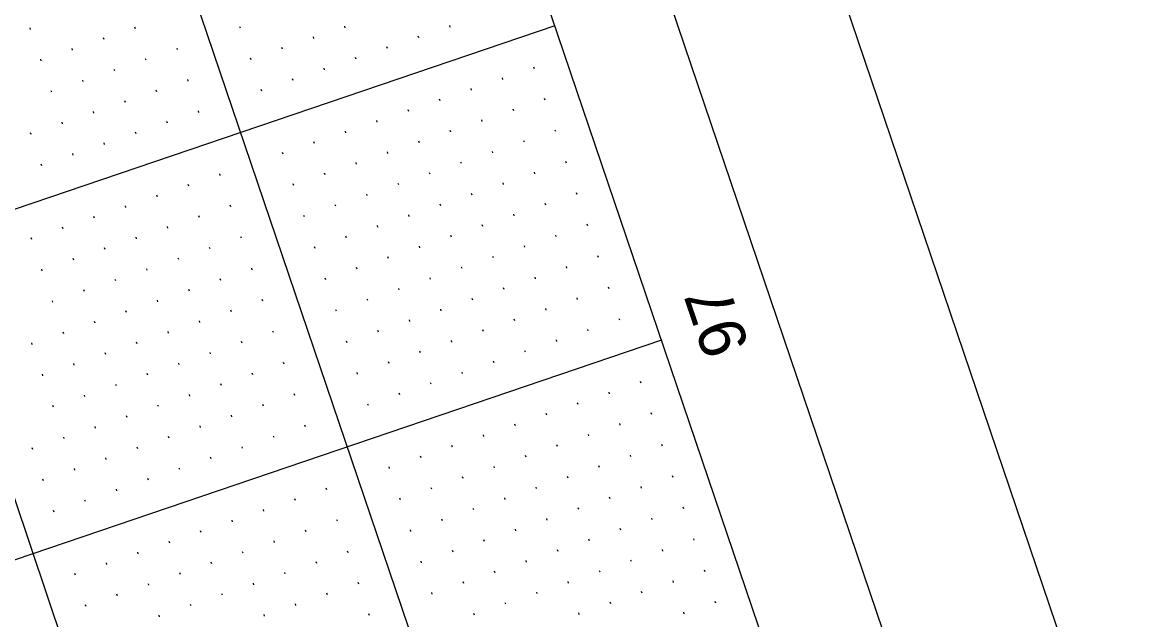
# Model space of a CAD drawing. Extents: x 2150318 to 2152065, y 143281 to 145371.
# Drawn here: x 2151482.1 to 2151649.1, y 144649.2 to 144739.2 of the extents above; entities that cross this region are included whole.
import ezdxf

# ---------------------------------------------------------------- set-up
doc = ezdxf.new("R2010")
doc.units = 0
for name, color, linetype in [('SHT_Plan_Profile_Sheet_Sta_Txt', 7, 'Continuous'), ('SHT_Plot_Shape_Half', 7, 'Continuous'), ('SHT_Profile_Grid_Major', 7, 'Continuous'), ('SHT_Profile_Grid_Minor', 7, 'Continuous'), ('SHT_Sheet_Border', 7, 'Continuous')]:
    doc.layers.add(name, color=color, linetype=linetype)

msp = doc.modelspace()

# ---------------------------------------------------------------- linework, layer by layer
at = {"layer": 'SHT_Plot_Shape_Half'}
msp.add_lwpolyline([(2150909.49, 143371.4), (2150363.35, 144981.29), (2151405.04, 145334.68), (2151951.18, 143724.79)], close=True, dxfattribs=at)
at = {"layer": 'SHT_Profile_Grid_Major'}
for p, q in [((2151832.26, 143787.41), (2151326.27, 145278.92)), ((2151784.91, 143771.34), (2151278.93, 145262.85)), ((2151562.37, 144738.62), (2151088.87, 144577.99)), ((2151578.43, 144691.27), (2151147.55, 144545.1))]:
    msp.add_line(p, q, dxfattribs=at)
at = {"layer": 'SHT_Profile_Grid_Minor'}
for p, q in [((2151483.35, 144738.08), (2151483.27, 144738.32)), ((2151499.16, 144738.17), (2151499.08, 144738.41)), ((2151514.97, 144738.25), (2151514.89, 144738.49)), ((2151530.78, 144738.34), (2151530.7, 144738.57)), ((2151546.6, 144738.42), (2151546.51, 144738.66)), ((2151494.43, 144736.56), (2151494.35, 144736.8)), ((2151526.05, 144736.73), (2151525.97, 144736.97)), ((2151541.86, 144736.81), (2151541.78, 144737.05)), ((2151489.69, 144734.96), (2151489.61, 144735.19)), ((2151505.5, 144735.04), (2151505.42, 144735.28)), ((2151521.31, 144735.12), (2151521.23, 144735.36)), ((2151537.13, 144735.21), (2151537.04, 144735.44)), ((2151484.96, 144733.35), (2151484.88, 144733.59)), ((2151500.77, 144733.43), (2151500.69, 144733.67)), ((2151516.58, 144733.52), (2151516.5, 144733.75)), ((2151532.39, 144733.6), (2151532.31, 144733.84)), ((2151496.03, 144731.83), (2151495.95, 144732.06)), ((2151527.66, 144732), (2151527.58, 144732.23)), ((2151559.28, 144732.16), (2151559.2, 144732.4)), ((2151491.3, 144730.22), (2151491.22, 144730.46)), ((2151507.11, 144730.3), (2151507.03, 144730.54)), ((2151522.92, 144730.39), (2151522.84, 144730.63)), ((2151554.54, 144730.56), (2151554.46, 144730.79)), ((2151486.56, 144728.61), (2151486.48, 144728.85)), ((2151502.37, 144728.7), (2151502.29, 144728.94)), ((2151518.19, 144728.78), (2151518.11, 144729.02)), ((2151549.81, 144728.95), (2151549.73, 144729.19)), ((2151497.64, 144727.09), (2151497.56, 144727.33)), ((2151545.07, 144727.34), (2151544.99, 144727.58)), ((2151556.15, 144725.82), (2151556.07, 144726.06)), ((2151560.88, 144727.43), (2151560.8, 144727.67)), ((2151492.9, 144725.49), (2151492.82, 144725.72)), ((2151508.72, 144725.57), (2151508.64, 144725.81)), ((2151535.6, 144724.13), (2151535.52, 144724.37)), ((2151540.34, 144725.74), (2151540.26, 144725.97)), ((2151551.41, 144724.22), (2151551.33, 144724.45)), ((2151488.17, 144723.88), (2151488.09, 144724.12)), ((2151503.98, 144723.96), (2151503.9, 144724.2)), ((2151530.87, 144722.53), (2151530.79, 144722.76)), ((2151546.68, 144722.61), (2151546.6, 144722.85)), ((2151562.49, 144722.69), (2151562.41, 144722.93)), ((2151483.43, 144722.27), (2151483.35, 144722.51)), ((2151499.25, 144722.36), (2151499.17, 144722.59)), ((2151526.13, 144720.92), (2151526.05, 144721.16)), ((2151541.94, 144721), (2151541.86, 144721.24)), ((2151557.76, 144721.09), (2151557.68, 144721.32)), ((2151489.78, 144719.14), (2151489.7, 144719.38)), ((2151494.51, 144720.75), (2151494.43, 144720.99)), ((2151521.4, 144719.31), (2151521.32, 144719.55)), ((2151537.21, 144719.4), (2151537.13, 144719.63)), ((2151553.02, 144719.48), (2151552.94, 144719.72)), ((2151485.04, 144717.54), (2151484.96, 144717.78)), ((2151532.47, 144717.79), (2151532.39, 144718.03)), ((2151548.29, 144717.87), (2151548.21, 144718.11)), ((2151564.1, 144717.96), (2151564.02, 144718.2)), ((2151511.93, 144716.1), (2151511.85, 144716.34)), ((2151527.74, 144716.18), (2151527.66, 144716.42)), ((2151543.55, 144716.27), (2151543.47, 144716.5)), ((2151559.36, 144716.35), (2151559.28, 144716.59)), ((2151507.19, 144714.49), (2151507.11, 144714.73)), ((2151523, 144714.58), (2151522.92, 144714.81)), ((2151538.82, 144714.66), (2151538.74, 144714.9)), ((2151554.63, 144714.75), (2151554.55, 144714.98)), ((2151502.46, 144712.89), (2151502.38, 144713.12)), ((2151534.08, 144713.06), (2151534, 144713.29)), ((2151549.89, 144713.14), (2151549.81, 144713.38)), ((2151565.7, 144713.22), (2151565.62, 144713.46)), ((2151497.72, 144711.28), (2151497.64, 144711.52)), ((2151513.53, 144711.37), (2151513.45, 144711.6)), ((2151529.35, 144711.45), (2151529.27, 144711.69)), ((2151545.16, 144711.53), (2151545.08, 144711.77)), ((2151560.97, 144711.62), (2151560.89, 144711.85)), ((2151492.99, 144709.67), (2151492.91, 144709.91)), ((2151508.8, 144709.76), (2151508.72, 144710)), ((2151524.61, 144709.84), (2151524.53, 144710.08)), ((2151540.42, 144709.93), (2151540.34, 144710.16)), ((2151556.23, 144710.01), (2151556.15, 144710.25)), ((2151488.25, 144708.07), (2151488.17, 144708.31)), ((2151504.06, 144708.15), (2151503.98, 144708.39)), ((2151535.69, 144708.32), (2151535.61, 144708.56)), ((2151551.5, 144708.4), (2151551.42, 144708.64)), ((2151567.31, 144708.49), (2151567.23, 144708.73)), ((2151483.52, 144706.46), (2151483.44, 144706.7)), ((2151499.33, 144706.55), (2151499.25, 144706.78)), ((2151515.14, 144706.63), (2151515.06, 144706.87)), ((2151530.95, 144706.71), (2151530.87, 144706.95)), ((2151546.76, 144706.8), (2151546.68, 144707.03)), ((2151562.57, 144706.88), (2151562.49, 144707.12)), ((2151494.59, 144704.94), (2151494.51, 144705.18)), ((2151510.41, 144705.02), (2151510.33, 144705.26)), ((2151526.22, 144705.11), (2151526.14, 144705.34)), ((2151542.03, 144705.19), (2151541.95, 144705.43)), ((2151557.84, 144705.28), (2151557.76, 144705.51)), ((2151489.86, 144703.33), (2151489.78, 144703.57)), ((2151505.67, 144703.42), (2151505.59, 144703.65)), ((2151537.29, 144703.59), (2151537.21, 144703.82)), ((2151553.1, 144703.67), (2151553.02, 144703.91)), ((2151568.92, 144703.75), (2151568.84, 144703.99)), ((2151485.12, 144701.73), (2151485.04, 144701.96)), ((2151500.94, 144701.81), (2151500.86, 144702.05)), ((2151516.75, 144701.9), (2151516.67, 144702.13)), ((2151532.56, 144701.98), (2151532.48, 144702.22)), ((2151548.37, 144702.06), (2151548.29, 144702.3)), ((2151564.18, 144702.15), (2151564.1, 144702.38)), ((2151496.2, 144700.2), (2151496.12, 144700.44)), ((2151512.01, 144700.29), (2151511.93, 144700.53)), ((2151527.82, 144700.37), (2151527.74, 144700.61)), ((2151543.63, 144700.46), (2151543.55, 144700.69)), ((2151559.45, 144700.54), (2151559.37, 144700.78)), ((2151491.47, 144698.6), (2151491.39, 144698.84)), ((2151507.28, 144698.68), (2151507.2, 144698.92)), ((2151538.9, 144698.85), (2151538.82, 144699.09)), ((2151554.71, 144698.93), (2151554.63, 144699.17)), ((2151565.79, 144697.41), (2151565.71, 144697.65)), ((2151570.52, 144699.02), (2151570.44, 144699.26)), ((2151486.73, 144696.99), (2151486.65, 144697.23)), ((2151502.54, 144697.08), (2151502.46, 144697.31)), ((2151518.35, 144697.16), (2151518.27, 144697.4)), ((2151534.16, 144697.24), (2151534.08, 144697.48)), ((2151545.24, 144695.72), (2151545.16, 144695.96)), ((2151549.98, 144697.33), (2151549.9, 144697.57)), ((2151561.05, 144695.81), (2151560.97, 144696.04)), ((2151497.81, 144695.47), (2151497.73, 144695.71)), ((2151513.62, 144695.55), (2151513.54, 144695.79)), ((2151529.43, 144695.64), (2151529.35, 144695.87)), ((2151540.51, 144694.12), (2151540.43, 144694.35)), ((2151556.32, 144694.2), (2151556.24, 144694.44)), ((2151572.13, 144694.28), (2151572.05, 144694.52)), ((2151493.07, 144693.86), (2151492.99, 144694.1)), ((2151508.88, 144693.95), (2151508.8, 144694.18)), ((2151519.96, 144692.43), (2151519.88, 144692.66)), ((2151535.77, 144692.51), (2151535.69, 144692.75)), ((2151551.58, 144692.59), (2151551.5, 144692.83)), ((2151567.39, 144692.68), (2151567.31, 144692.91)), ((2151488.34, 144692.26), (2151488.26, 144692.49)), ((2151499.41, 144690.74), (2151499.33, 144690.97)), ((2151504.15, 144692.34), (2151504.07, 144692.58)), ((2151515.22, 144690.82), (2151515.14, 144691.06)), ((2151531.04, 144690.9), (2151530.96, 144691.14)), ((2151546.85, 144690.99), (2151546.77, 144691.22)), ((2151562.66, 144691.07), (2151562.58, 144691.31)), ((2151483.6, 144690.65), (2151483.52, 144690.89)), ((2151494.68, 144689.13), (2151494.6, 144689.37)), ((2151510.49, 144689.21), (2151510.41, 144689.45)), ((2151542.11, 144689.38), (2151542.03, 144689.62)), ((2151557.92, 144689.46), (2151557.84, 144689.7)), ((2151489.94, 144687.52), (2151489.86, 144687.76)), ((2151505.75, 144687.61), (2151505.67, 144687.84)), ((2151521.57, 144687.69), (2151521.49, 144687.93)), ((2151537.38, 144687.77), (2151537.3, 144688.01)), ((2151553.19, 144687.86), (2151553.11, 144688.1)), ((2151485.21, 144685.92), (2151485.13, 144686.15)), ((2151501.02, 144686), (2151500.94, 144686.24)), ((2151516.83, 144686.08), (2151516.75, 144686.32)), ((2151532.64, 144686.17), (2151532.56, 144686.4)), ((2151548.45, 144686.25), (2151548.37, 144686.49)), ((2151496.29, 144684.39), (2151496.2, 144684.63)), ((2151512.1, 144684.48), (2151512.02, 144684.71)), ((2151543.72, 144684.65), (2151543.64, 144684.88)), ((2151575.34, 144684.81), (2151575.26, 144685.05)), ((2151491.55, 144682.79), (2151491.47, 144683.02)), ((2151507.36, 144682.87), (2151507.28, 144683.11)), ((2151523.17, 144682.96), (2151523.09, 144683.19)), ((2151538.98, 144683.04), (2151538.9, 144683.28)), ((2151570.61, 144683.21), (2151570.53, 144683.44)), ((2151486.82, 144681.18), (2151486.73, 144681.42)), ((2151502.63, 144681.27), (2151502.55, 144681.5)), ((2151518.44, 144681.35), (2151518.36, 144681.59)), ((2151534.25, 144681.43), (2151534.17, 144681.67)), ((2151565.87, 144681.6), (2151565.79, 144681.84)), ((2151497.89, 144679.66), (2151497.81, 144679.9)), ((2151513.7, 144679.74), (2151513.62, 144679.98)), ((2151561.14, 144679.99), (2151561.06, 144680.23)), ((2151576.95, 144680.08), (2151576.87, 144680.32)), ((2151493.16, 144678.05), (2151493.08, 144678.29)), ((2151508.97, 144678.14), (2151508.89, 144678.37)), ((2151524.78, 144678.22), (2151524.7, 144678.46)), ((2151556.4, 144678.39), (2151556.32, 144678.63)), ((2151572.21, 144678.47), (2151572.13, 144678.71)), ((2151488.42, 144676.45), (2151488.34, 144676.68)), ((2151504.23, 144676.53), (2151504.15, 144676.77)), ((2151520.04, 144676.61), (2151519.96, 144676.85)), ((2151551.67, 144676.78), (2151551.59, 144677.02)), ((2151567.48, 144676.87), (2151567.4, 144677.1)), ((2151483.69, 144674.84), (2151483.61, 144675.08)), ((2151499.5, 144674.92), (2151499.42, 144675.16)), ((2151515.31, 144675.01), (2151515.23, 144675.24)), ((2151546.93, 144675.18), (2151546.85, 144675.41)), ((2151562.74, 144675.26), (2151562.66, 144675.5)), ((2151578.55, 144675.34), (2151578.47, 144675.58)), ((2151494.76, 144673.32), (2151494.68, 144673.55)), ((2151510.57, 144673.4), (2151510.49, 144673.64)), ((2151542.2, 144673.57), (2151542.12, 144673.81)), ((2151558.01, 144673.65), (2151557.93, 144673.89)), ((2151573.82, 144673.74), (2151573.74, 144673.97)), ((2151490.03, 144671.71), (2151489.95, 144671.95)), ((2151505.84, 144671.8), (2151505.76, 144672.03)), ((2151537.46, 144671.96), (2151537.38, 144672.2)), ((2151553.27, 144672.05), (2151553.19, 144672.28)), ((2151569.08, 144672.13), (2151569, 144672.37)), ((2151485.29, 144670.1), (2151485.21, 144670.34)), ((2151501.1, 144670.19), (2151501.02, 144670.43)), ((2151548.54, 144670.44), (2151548.46, 144670.68)), ((2151564.35, 144670.52), (2151564.27, 144670.76)), ((2151575.42, 144669), (2151575.34, 144669.24)), ((2151580.16, 144670.61), (2151580.08, 144670.85)), ((2151496.37, 144668.58), (2151496.29, 144668.82)), ((2151527.99, 144668.75), (2151527.91, 144668.99)), ((2151543.8, 144668.83), (2151543.72, 144669.07)), ((2151554.88, 144667.31), (2151554.8, 144667.55)), ((2151559.61, 144668.92), (2151559.53, 144669.16)), ((2151570.69, 144667.4), (2151570.61, 144667.63)), ((2151491.63, 144666.98), (2151491.55, 144667.21)), ((2151523.26, 144667.14), (2151523.18, 144667.38)), ((2151539.07, 144667.23), (2151538.99, 144667.47)), ((2151550.14, 144665.71), (2151550.06, 144665.94)), ((2151565.95, 144665.79), (2151565.87, 144666.03)), ((2151581.77, 144665.87), (2151581.69, 144666.11)), ((2151486.9, 144665.37), (2151486.82, 144665.61)), ((2151518.52, 144665.54), (2151518.44, 144665.77)), ((2151529.6, 144664.02), (2151529.52, 144664.25)), ((2151545.41, 144664.1), (2151545.33, 144664.34)), ((2151561.22, 144664.18), (2151561.14, 144664.42)), ((2151577.03, 144664.27), (2151576.95, 144664.5)), ((2151509.05, 144662.33), (2151508.97, 144662.56)), ((2151513.79, 144663.93), (2151513.71, 144664.17)), ((2151524.86, 144662.41), (2151524.78, 144662.65)), ((2151540.67, 144662.49), (2151540.59, 144662.73)), ((2151556.49, 144662.58), (2151556.4, 144662.81)), ((2151572.3, 144662.66), (2151572.22, 144662.9)), ((2151504.32, 144660.72), (2151504.24, 144660.96)), ((2151520.13, 144660.8), (2151520.05, 144661.04)), ((2151551.75, 144660.97), (2151551.67, 144661.21)), ((2151567.56, 144661.06), (2151567.48, 144661.29)), ((2151583.37, 144661.14), (2151583.29, 144661.38)), ((2151499.58, 144659.11), (2151499.5, 144659.35)), ((2151515.39, 144659.2), (2151515.31, 144659.43)), ((2151531.2, 144659.28), (2151531.12, 144659.52)), ((2151547.02, 144659.36), (2151546.93, 144659.6)), ((2151562.83, 144659.45), (2151562.75, 144659.69)), ((2151578.64, 144659.53), (2151578.56, 144659.77)), ((2151494.85, 144657.51), (2151494.77, 144657.74)), ((2151510.66, 144657.59), (2151510.58, 144657.83)), ((2151526.47, 144657.67), (2151526.39, 144657.91)), ((2151542.28, 144657.76), (2151542.2, 144658)), ((2151558.09, 144657.84), (2151558.01, 144658.08)), ((2151573.9, 144657.93), (2151573.82, 144658.16)), ((2151490.11, 144655.9), (2151490.03, 144656.14)), ((2151505.92, 144655.98), (2151505.84, 144656.22)), ((2151521.73, 144656.07), (2151521.65, 144656.3)), ((2151553.36, 144656.24), (2151553.28, 144656.47)), ((2151569.17, 144656.32), (2151569.09, 144656.56)), ((2151584.98, 144656.4), (2151584.9, 144656.64)), ((2151501.19, 144654.38), (2151501.11, 144654.61)), ((2151517, 144654.46), (2151516.92, 144654.7)), ((2151532.81, 144654.55), (2151532.73, 144654.78)), ((2151548.62, 144654.63), (2151548.54, 144654.87)), ((2151564.43, 144654.71), (2151564.35, 144654.95)), ((2151580.24, 144654.8), (2151580.16, 144655.03)), ((2151496.45, 144652.77), (2151496.37, 144653.01)), ((2151512.26, 144652.86), (2151512.18, 144653.09)), ((2151528.08, 144652.94), (2151528, 144653.18)), ((2151543.89, 144653.02), (2151543.81, 144653.26)), ((2151559.7, 144653.11), (2151559.62, 144653.34)), ((2151575.51, 144653.19), (2151575.43, 144653.43)), ((2151491.72, 144651.17), (2151491.64, 144651.4)), ((2151507.53, 144651.25), (2151507.45, 144651.49)), ((2151523.34, 144651.33), (2151523.26, 144651.57)), ((2151554.96, 144651.5), (2151554.88, 144651.74)), ((2151570.77, 144651.59), (2151570.69, 144651.82)), ((2151586.59, 144651.67), (2151586.5, 144651.91)), ((2151502.79, 144649.64), (2151502.71, 144649.88)), ((2151518.61, 144649.73), (2151518.53, 144649.96)), ((2151534.42, 144649.81), (2151534.34, 144650.05)), ((2151550.23, 144649.89), (2151550.15, 144650.13)), ((2151566.04, 144649.98), (2151565.96, 144650.22)), ((2151581.85, 144650.06), (2151581.77, 144650.3))]:
    msp.add_line(p, q, dxfattribs=at)
at = {"layer": 'SHT_Sheet_Border'}
msp.add_line((2151879.61, 143803.47), (2151457.96, 145046.39), dxfattribs=at)
msp.add_lwpolyline([(2150901.85, 143471.77), (2150395.86, 144963.28), (2151390.2, 145300.6), (2151896.19, 143809.09)], close=True, dxfattribs=at)

# ---------------------------------------------------------------- texts
at = {"layer": 'SHT_Plan_Profile_Sheet_Sta_Txt'}
msp.add_text('97', height=7, rotation=108.7393, dxfattribs=at).set_placement((2151591.7, 144690.3))

doc.saveas('drawing.dxf')
